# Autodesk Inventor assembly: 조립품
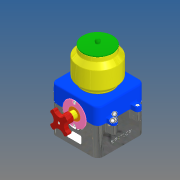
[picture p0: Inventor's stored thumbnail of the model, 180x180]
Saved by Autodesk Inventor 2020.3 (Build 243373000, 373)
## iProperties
Created: 2022-03
Part Number: 조립품
Document SubType Name: Assembly
Designer: EZDESIGN
Author: EZDESIGN
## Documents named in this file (11)
- C:\Users\EZDESIGN\Desktop\720306V1019\720306V1019\조립품.iam
- C:\Users\EZDESIGN\Desktop\720306V1019\720306V1019\본체.ipt
- C:\Users\EZDESIGN\Desktop\720306V1019\720306V1019\본체커버.ipt
- C:\Users\EZDESIGN\Desktop\720306V1019\720306V1019\핸들축.ipt
- C:\Users\EZDESIGN\Desktop\720306V1019\720306V1019\앞커버.ipt
- C:\Users\EZDESIGN\Desktop\720306V1019\720306V1019\베어링 부시.ipt
- C:\Users\EZDESIGN\Desktop\720306V1019\720306V1019\용기.ipt
- C:\Users\EZDESIGN\Desktop\720306V1019\720306V1019\용기캡.ipt
- C:\Users\EZDESIGN\Desktop\720306V1019\720306V1019\핸들.ipt
- C:\Users\EZDESIGN\Desktop\720306V1019\720306V1019\볼트 M3x12.ipt
- C:\Users\EZDESIGN\Desktop\720306V1019\720306V1019\볼트 M4x12.ipt
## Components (2 placed, 2 different names)
1. 핸들축:1 — 각도:1
2. 핸들:1
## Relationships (1: Angle 1)
- 각도:1 [Angle]: 핸들축:1
